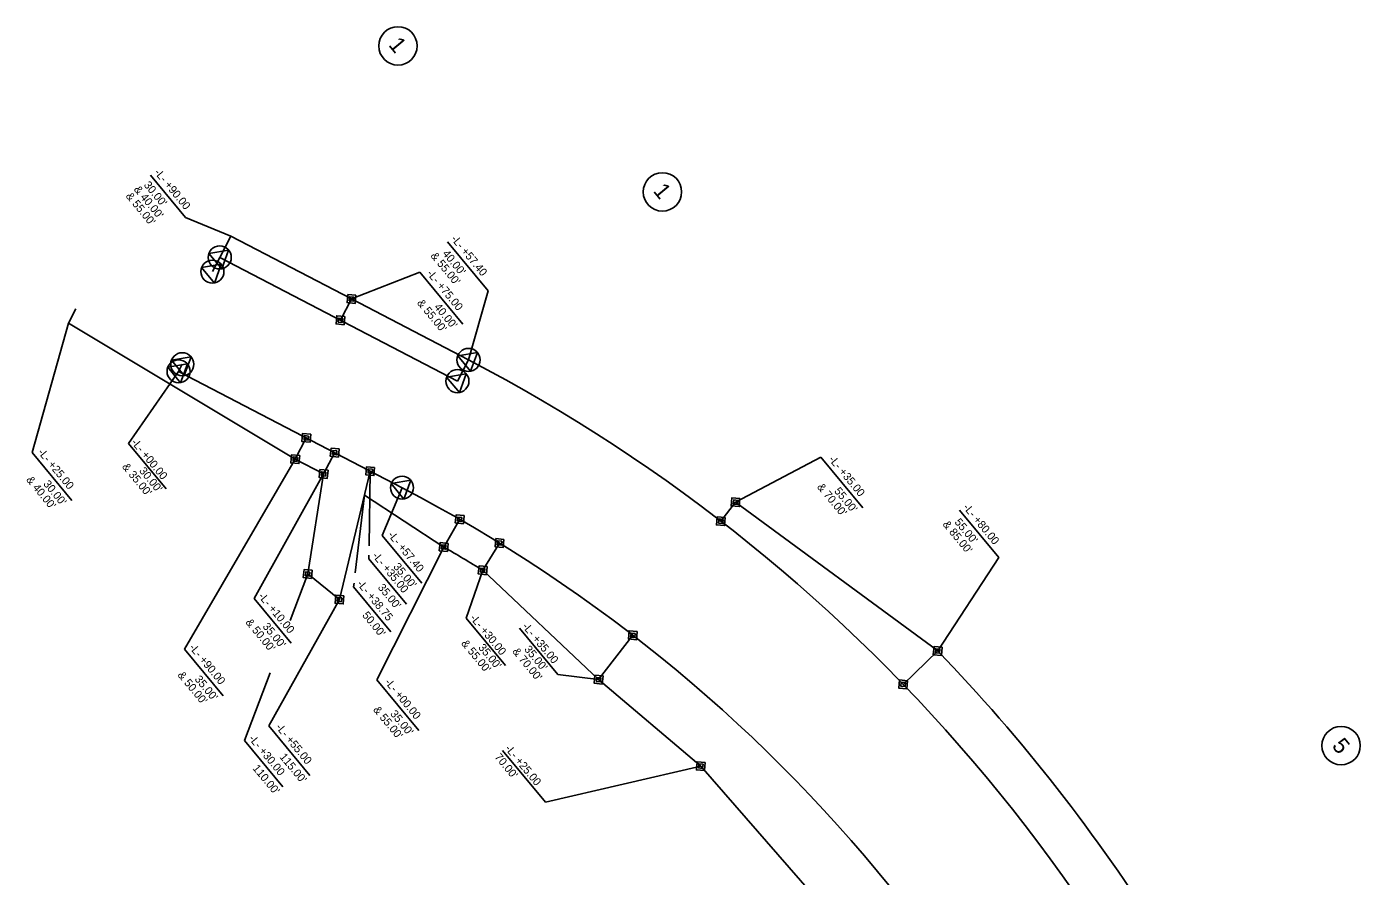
# Model space of a CAD drawing. Extents: x 2058303 to 2059235, y 688152 to 689231.
# Drawn here: x 2058303 to 2059136, y 688700 to 689231 of the extents above; entities that cross this region are included whole.
import ezdxf

# ---------------------------------------------------------------- set-up
doc = ezdxf.new("R2010")
doc.units = 0
for name, color, linetype in [('Prop Easement Aerial Utility', 7, 'Continuous'), ('Prop Easement Aerial Utility Station Offsets', 7, 'Continuous'), ('Prop Easement Construction', 7, 'Continuous'), ('Prop Easement Construction Station Offsets', 7, 'Continuous'), ('Prop Easement Permanent Drainage', 7, 'Continuous'), ('Prop Easement Permanent Drainage Station Offsets', 7, 'Continuous'), ('Prop Easement Permanent Drainage Utility', 7, 'Continuous'), ('Prop Easement Permanent Drainage Utility Station Offsets', 7, 'Continuous'), ('Prop Easement Permanent Utility', 7, 'Continuous'), ('Prop Easement Permanent Utility Station Offsets', 7, 'Continuous'), ('Prop Parcel Number CELL', 7, 'Continuous'), ('Prop Parcel Number Text', 7, 'Continuous'), ('Prop ROW Marker CELL', 7, 'Continuous'), ('Prop ROW Permanent Easement CELL', 7, 'Continuous'), ('Prop ROW RW Lines', 7, 'Continuous'), ('Prop ROW Station Offsets', 7, 'Continuous')]:
    doc.layers.add(name, color=color, linetype=linetype)

msp = doc.modelspace()

# ---------------------------------------------------------------- linework, layer by layer
at = {"layer": 'Prop Easement Aerial Utility'}
for p, q in [((2058488.1, 688951.28), (2058478.14, 688888.83)), ((2058517.2, 688953.05), (2058498.01, 688872.85)), ((2058478.14, 688888.83), (2058498.01, 688872.85))]:
    msp.add_line(p, q, dxfattribs=at)
at = {"layer": 'Prop Easement Aerial Utility Station Offsets'}
for p, q in [((2058517.2, 688953.05), (2058516.48, 688906.48)), ((2058516.39, 688900.55), (2058516.36, 688898.32)), ((2058516.36, 688898.32), (2058539.84, 688870.01)), ((2058478.14, 688888.83), (2058467.11, 688859.72)), ((2058498.01, 688872.85), (2058453.75, 688793.98)), ((2058454.71, 688827.03), (2058438.67, 688784.73)), ((2058453.75, 688793.98), (2058479.47, 688762.95)), ((2058438.67, 688784.73), (2058462.61, 688755.87))]:
    msp.add_line(p, q, dxfattribs=at)
at = {"layer": 'Prop Easement Construction'}
for p, q in [((2058423.2, 689086.52), (2058430.13, 689099.82)), ((2058430.13, 689099.82), (2058505.53, 689060.58)), ((2058333.23, 689054.43), (2058328.61, 689045.56)), ((2058328.61, 689045.56), (2058470.36, 688960.52)), ((2058513.6, 688938.01), (2058563.14, 688905.63)), ((2058587.49, 688891.11), (2058659.9, 688822.83))]:
    msp.add_line(p, q, dxfattribs=at)
at = {"layer": 'Prop Easement Construction Station Offsets'}
for p, q in [((2058401.83, 689111.53), (2058380, 689137.85)), ((2058430.13, 689099.82), (2058401.83, 689111.53)), ((2058328.61, 689045.56), (2058306.02, 688964.6)), ((2058306.02, 688964.6), (2058330.82, 688934.7)), ((2058513.6, 688938.01), (2058507.89, 688889.53)), ((2058507.13, 688883.13), (2058506.84, 688880.69)), ((2058506.84, 688880.69), (2058530.09, 688852.66))]:
    msp.add_line(p, q, dxfattribs=at)
at = {"layer": 'Prop Easement Permanent Drainage'}
for p, q in [((2058477.28, 688973.82), (2058470.36, 688960.52)), ((2058470.36, 688960.52), (2058488.1, 688951.28)), ((2058488.1, 688951.28), (2058495.02, 688964.59)), ((2058573.12, 688922.96), (2058563.14, 688905.63)), ((2058587.49, 688891.11), (2058597.99, 688908.14)), ((2058681.29, 688850.54), (2058659.9, 688822.83)), ((2058659.9, 688822.83), (2058723.77, 688768.77)), ((2058723.77, 688768.77), (2058830.47, 688646.47))]:
    msp.add_line(p, q, dxfattribs=at)
msp.add_arc((2058091.57, 688086.7), 945, 58.34591, 60.06478, dxfattribs=at)
at = {"layer": 'Prop Easement Permanent Drainage Station Offsets'}
for p, q in [((2058470.36, 688960.52), (2058401.24, 688841.87)), ((2058488.1, 688951.28), (2058444.72, 688873.54)), ((2058563.14, 688905.63), (2058521.42, 688822.6)), ((2058587.49, 688891.11), (2058577.2, 688861.22)), ((2058444.72, 688873.54), (2058467.85, 688845.65)), ((2058577.2, 688861.22), (2058601.66, 688831.72)), ((2058634.51, 688825.98), (2058610.56, 688854.86)), ((2058401.24, 688841.87), (2058425.4, 688812.73)), ((2058659.9, 688822.83), (2058634.51, 688825.98)), ((2058521.42, 688822.6), (2058547.58, 688791.06)), ((2058626.72, 688746.18), (2058599.9, 688778.52)), ((2058723.77, 688768.77), (2058626.72, 688746.18))]:
    msp.add_line(p, q, dxfattribs=at)
at = {"layer": 'Prop Easement Permanent Drainage Utility'}
msp.add_line((2058850.19, 688819.85), (2058871.76, 688840.7), dxfattribs=at)
msp.add_arc((2058091.57, 688086.7), 1085, 31.98985, 44.02196, dxfattribs=at)
at = {"layer": 'Prop Easement Permanent Drainage Utility Station Offsets'}
for p, q in [((2058909.97, 688899.01), (2058885.38, 688928.66)), ((2058871.76, 688840.7), (2058909.97, 688899.01))]:
    msp.add_line(p, q, dxfattribs=at)
at = {"layer": 'Prop Easement Permanent Utility'}
for p, q in [((2058498.6, 689047.28), (2058505.53, 689060.58)), ((2058505.53, 689060.58), (2058578.62, 689022.54)), ((2058736.29, 688921.77), (2058745.46, 688933.65)), ((2058745.46, 688933.65), (2058871.76, 688840.7))]:
    msp.add_line(p, q, dxfattribs=at)
at = {"layer": 'Prop Easement Permanent Utility Station Offsets'}
for p, q in [((2058505.53, 689060.58), (2058548.13, 689077.26)), ((2058548.13, 689077.26), (2058575.08, 689044.77)), ((2058745.46, 688933.65), (2058798.78, 688961.82)), ((2058798.78, 688961.82), (2058824.98, 688930.22))]:
    msp.add_line(p, q, dxfattribs=at)
at = {"layer": 'Prop Parcel Number CELL'}
for p, q in [((2058534.52, 689218.65), (2058534.52, 689218.65)), ((2058699.79, 689127.45), (2058699.79, 689127.45)), ((2059123.83, 688781.61), (2059123.83, 688781.61))]:
    msp.add_line(p, q, dxfattribs=at)
for centre in [(2058534.52, 689218.65), (2058699.79, 689127.45), (2059123.83, 688781.61)]:
    msp.add_circle(centre, 12, dxfattribs=at)
at = {"layer": 'Prop ROW Marker CELL'}
for p, q in [((2058423.2, 689086.52), (2058423.2, 689086.52)), ((2058418.59, 689077.65), (2058418.59, 689077.65)), ((2058399.76, 689019.8), (2058399.76, 689019.8)), ((2058578.62, 689022.54), (2058578.62, 689022.54)), ((2058397.45, 689015.37), (2058397.45, 689015.37)), ((2058571.69, 689009.24), (2058571.69, 689009.24)), ((2058537.07, 688942.71), (2058537.07, 688942.71))]:
    msp.add_line(p, q, dxfattribs=at)
for points in [[(2058416.44, 689089.03), (2058428.74, 689091.11), (2058424.42, 689079.41)], [(2058411.82, 689080.16), (2058424.13, 689082.24), (2058419.8, 689070.54)], [(2058571.86, 689025.06), (2058584.16, 689027.14), (2058579.83, 689015.43)], [(2058390.69, 689017.88), (2058402.99, 689019.97), (2058398.67, 689008.26)], [(2058392.99, 689022.32), (2058405.3, 689024.4), (2058400.97, 689012.69)], [(2058564.93, 689011.75), (2058577.23, 689013.83), (2058572.91, 689002.13)], [(2058530.31, 688945.22), (2058542.61, 688947.3), (2058538.28, 688935.6)]]:
    msp.add_lwpolyline(points, close=True, dxfattribs=at)
for centre in [(2058423.2, 689086.52), (2058418.59, 689077.65), (2058399.76, 689019.8), (2058578.62, 689022.54), (2058397.45, 689015.37), (2058571.69, 689009.24), (2058537.07, 688942.71)]:
    msp.add_circle(centre, 7.2, dxfattribs=at)
at = {"layer": 'Prop ROW Permanent Easement CELL'}
for p, q in [((2058505.53, 689060.58), (2058505.53, 689060.58)), ((2058498.6, 689047.28), (2058498.6, 689047.28)), ((2058477.28, 688973.82), (2058477.28, 688973.82)), ((2058470.36, 688960.52), (2058470.36, 688960.52)), ((2058495.02, 688964.59), (2058495.02, 688964.59)), ((2058488.1, 688951.28), (2058488.1, 688951.28)), ((2058517.2, 688953.05), (2058517.2, 688953.05)), ((2058745.46, 688933.65), (2058745.46, 688933.65)), ((2058573.12, 688922.96), (2058573.12, 688922.96)), ((2058736.29, 688921.77), (2058736.29, 688921.77)), ((2058597.99, 688908.14), (2058597.99, 688908.14)), ((2058563.14, 688905.63), (2058563.14, 688905.63)), ((2058478.14, 688888.83), (2058478.14, 688888.83)), ((2058587.49, 688891.11), (2058587.49, 688891.11)), ((2058498.01, 688872.85), (2058498.01, 688872.85)), ((2058681.29, 688850.54), (2058681.29, 688850.54)), ((2058871.76, 688840.7), (2058871.76, 688840.7)), ((2058659.9, 688822.83), (2058659.9, 688822.83)), ((2058850.19, 688819.85), (2058850.19, 688819.85)), ((2058723.77, 688768.77), (2058723.77, 688768.77))]:
    msp.add_line(p, q, dxfattribs=at)
for points in [[(2058508.3, 689062.88), (2058507.82, 689057.81), (2058502.76, 689058.28), (2058503.23, 689063.35)], [(2058506.91, 689061.73), (2058506.68, 689059.2), (2058504.14, 689059.43), (2058504.38, 689061.97)], [(2058501.37, 689049.57), (2058500.9, 689044.5), (2058495.83, 689044.98), (2058496.3, 689050.05)], [(2058499.99, 689048.43), (2058499.75, 689045.89), (2058497.22, 689046.13), (2058497.45, 689048.66)], [(2058480.05, 688976.12), (2058479.58, 688971.05), (2058474.51, 688971.52), (2058474.99, 688976.59)], [(2058478.67, 688974.97), (2058478.43, 688972.44), (2058475.9, 688972.67), (2058476.13, 688975.21)], [(2058497.8, 688966.89), (2058497.32, 688961.82), (2058492.25, 688962.29), (2058492.73, 688967.36)], [(2058473.13, 688962.81), (2058472.66, 688957.74), (2058467.59, 688958.22), (2058468.06, 688963.29)], [(2058471.74, 688961.66), (2058471.51, 688959.13), (2058468.97, 688959.37), (2058469.21, 688961.9)], [(2058496.41, 688965.74), (2058496.17, 688963.2), (2058493.64, 688963.44), (2058493.88, 688965.97)], [(2058490.87, 688953.58), (2058490.4, 688948.51), (2058485.33, 688948.99), (2058485.8, 688954.05)], [(2058489.49, 688952.43), (2058489.25, 688949.9), (2058486.71, 688950.13), (2058486.95, 688952.67)], [(2058519.97, 688955.35), (2058519.5, 688950.28), (2058514.43, 688950.75), (2058514.9, 688955.82)], [(2058518.59, 688954.2), (2058518.35, 688951.66), (2058515.82, 688951.9), (2058516.05, 688954.43)], [(2058748.23, 688935.95), (2058747.76, 688930.88), (2058742.69, 688931.35), (2058743.16, 688936.42)], [(2058746.85, 688934.8), (2058746.61, 688932.26), (2058744.07, 688932.5), (2058744.31, 688935.03)], [(2058575.89, 688925.25), (2058575.42, 688920.19), (2058570.35, 688920.66), (2058570.82, 688925.73)], [(2058574.51, 688924.11), (2058574.27, 688921.57), (2058571.74, 688921.81), (2058571.97, 688924.34)], [(2058739.06, 688924.07), (2058738.59, 688919), (2058733.52, 688919.48), (2058733.99, 688924.55)], [(2058737.68, 688922.92), (2058737.44, 688920.39), (2058734.91, 688920.63), (2058735.14, 688923.16)], [(2058565.91, 688907.92), (2058565.44, 688902.85), (2058560.37, 688903.33), (2058560.84, 688908.4)], [(2058600.76, 688910.43), (2058600.29, 688905.36), (2058595.22, 688905.84), (2058595.69, 688910.91)], [(2058599.37, 688909.29), (2058599.14, 688906.75), (2058596.6, 688906.99), (2058596.84, 688909.52)], [(2058564.53, 688906.77), (2058564.29, 688904.24), (2058561.76, 688904.48), (2058561.99, 688907.01)], [(2058480.91, 688891.12), (2058480.44, 688886.05), (2058475.37, 688886.53), (2058475.84, 688891.6)], [(2058590.26, 688893.41), (2058589.79, 688888.34), (2058584.72, 688888.81), (2058585.19, 688893.88)], [(2058588.88, 688892.26), (2058588.64, 688889.73), (2058586.11, 688889.96), (2058586.34, 688892.5)], [(2058479.53, 688889.98), (2058479.29, 688887.44), (2058476.76, 688887.68), (2058476.99, 688890.21)], [(2058500.78, 688875.15), (2058500.31, 688870.08), (2058495.24, 688870.55), (2058495.71, 688875.62)], [(2058499.39, 688874), (2058499.16, 688871.46), (2058496.62, 688871.7), (2058496.86, 688874.23)], [(2058684.06, 688852.83), (2058683.59, 688847.76), (2058678.52, 688848.24), (2058678.99, 688853.31)], [(2058682.68, 688851.68), (2058682.44, 688849.15), (2058679.91, 688849.39), (2058680.14, 688851.92)], [(2058874.53, 688843), (2058874.06, 688837.93), (2058868.99, 688838.4), (2058869.46, 688843.47)], [(2058873.15, 688841.85), (2058872.91, 688839.32), (2058870.38, 688839.55), (2058870.61, 688842.09)], [(2058662.67, 688825.13), (2058662.2, 688820.06), (2058657.13, 688820.53), (2058657.61, 688825.6)], [(2058661.29, 688823.98), (2058661.05, 688821.45), (2058658.52, 688821.68), (2058658.75, 688824.22)], [(2058852.96, 688822.15), (2058852.49, 688817.08), (2058847.42, 688817.56), (2058847.89, 688822.62)], [(2058851.57, 688821), (2058851.34, 688818.47), (2058848.8, 688818.7), (2058849.04, 688821.24)], [(2058726.54, 688771.07), (2058726.06, 688766), (2058721, 688766.47), (2058721.47, 688771.54)], [(2058725.15, 688769.92), (2058724.91, 688767.39), (2058722.38, 688767.62), (2058722.62, 688770.16)]]:
    msp.add_lwpolyline(points, close=True, dxfattribs=at)
at = {"layer": 'Prop ROW RW Lines'}
for p, q in [((2058423.2, 689086.52), (2058418.59, 689077.65)), ((2058423.2, 689086.52), (2058571.69, 689009.24)), ((2058397.45, 689015.37), (2058399.76, 689019.8)), ((2058578.62, 689022.54), (2058571.69, 689009.24)), ((2058397.45, 689015.37), (2058537.07, 688942.71))]:
    msp.add_line(p, q, dxfattribs=at)
for radius, start in [(1055, 17.09295), (965, 13.85856)]:
    msp.add_arc((2058091.57, 688086.7), radius, start, 62.50587, dxfattribs=at)
at = {"layer": 'Prop ROW Station Offsets'}
for p, q in [((2058590.81, 689065.75), (2058565.43, 689096.36)), ((2058578.62, 689022.54), (2058590.81, 689065.75)), ((2058397.45, 689015.37), (2058366.24, 688970.33)), ((2058366.24, 688970.33), (2058389.73, 688942)), ((2058537.07, 688942.71), (2058524.72, 688912.92)), ((2058524.72, 688912.92), (2058549.52, 688883.02))]:
    msp.add_line(p, q, dxfattribs=at)

# ---------------------------------------------------------------- texts
at = {"layer": 'Prop Easement Aerial Utility Station Offsets'}
for s, p in [('-L- +35.00', (2058518.18, 688900.04)), ("35.00'", (2058521.63, 688880.22)), ('-L- +55.00', (2058457.82, 688792.99)), ('-L- +30.00', (2058440.95, 688785.9)), ("115.00'", (2058460.27, 688774.36)), ("110.00'", (2058443.41, 688767.27))]:
    msp.add_text(s, height=5, rotation=309.66721, dxfattribs=at).set_placement(p)
at = {"layer": 'Prop Easement Construction Station Offsets'}
for s, p in [(" 30.00'", (2058374.23, 689133.06)), ('-L- +90.00', (2058381.93, 689139.45)), ("& 55.00'", (2058364.14, 689124.7)), ("& 40.00'", (2058369.18, 689128.88)), ('-L- +25.00', (2058309.16, 688964.73)), ("& 40.00'", (2058301.96, 688947.48)), ("30.00'", (2058312.61, 688944.9)), ('-L- +38.75', (2058508.54, 688882.56)), ("50.00'", (2058511.89, 688862.86))]:
    msp.add_text(s, height=5, rotation=309.66721, dxfattribs=at).set_placement(p)
at = {"layer": 'Prop Easement Permanent Drainage Station Offsets'}
for s, p in [('-L- +10.00', (2058446.96, 688874.76)), ("& 50.00'", (2058438.99, 688858.43)), ("35.00'", (2058449.64, 688855.85)), ('-L- +30.00', (2058579.27, 688861.14)), ('-L- +35.00', (2058611.85, 688855.93)), ('-L- +90.00', (2058403.75, 688842.77)), ("& 55.00'", (2058573.75, 688845.29)), ("35.00'", (2058584.4, 688842.71)), ("& 70.00'", (2058605.71, 688840.27)), ("  35.00'", (2058610.75, 688844.46)), ("& 50.00'", (2058396.55, 688825.52)), ("35.00'", (2058407.2, 688822.94)), ('-L- +00.00', (2058525.92, 688821.09)), ("& 55.00'", (2058518.72, 688803.85)), ("35.00'", (2058529.37, 688801.27)), ("70.00'", (2058594.6, 688774.32)), ('-L- +25.00', (2058601.05, 688779.67))]:
    msp.add_text(s, height=5, rotation=309.66721, dxfattribs=at).set_placement(p)
at = {"layer": 'Prop Easement Permanent Drainage Utility Station Offsets'}
for s, p in [('-L- +80.00', (2058887.31, 688930.26)), ("& 85.00'", (2058874.56, 688919.69)), ("  55.00'", (2058879.61, 688923.88))]:
    msp.add_text(s, height=5, rotation=309.66721, dxfattribs=at).set_placement(p)
at = {"layer": 'Prop Easement Permanent Utility Station Offsets'}
for s, p in [('-L- +75.00', (2058552.23, 689076.37)), ("& 55.00'", (2058546.16, 689057.92)), ("40.00'", (2058556.81, 689055.34)), ('-L- +35.00', (2058803.33, 688960.26)), ("& 70.00'", (2058796.12, 688943.01)), ("55.00'", (2058806.78, 688940.43))]:
    msp.add_text(s, height=5, rotation=309.66721, dxfattribs=at).set_placement(p)
at = {"layer": 'Prop Parcel Number Text'}
for s, p in [('1', (2058528.22, 689219.06)), ('1', (2058693.6, 689127.81)), ('5', (2059117.68, 688781.19))]:
    msp.add_text(s, height=10, rotation=309.66721, dxfattribs=at).set_placement(p)
at = {"layer": 'Prop ROW Station Offsets'}
for s, p in [('-L- +57.40', (2058567.36, 689097.96)), ("& 55.00'", (2058554.61, 689087.39)), ("  40.00'", (2058559.66, 689091.57)), ('-L- +00.00', (2058367.57, 688970.83)), ("& 35.00'", (2058361.86, 688955.64)), ("30.00'", (2058372.52, 688953.06)), ('-L- +57.40', (2058527.86, 688913.05)), ("35.00'", (2058531.31, 688893.22))]:
    msp.add_text(s, height=5, rotation=309.66721, dxfattribs=at).set_placement(p)

doc.saveas('drawing.dxf')
